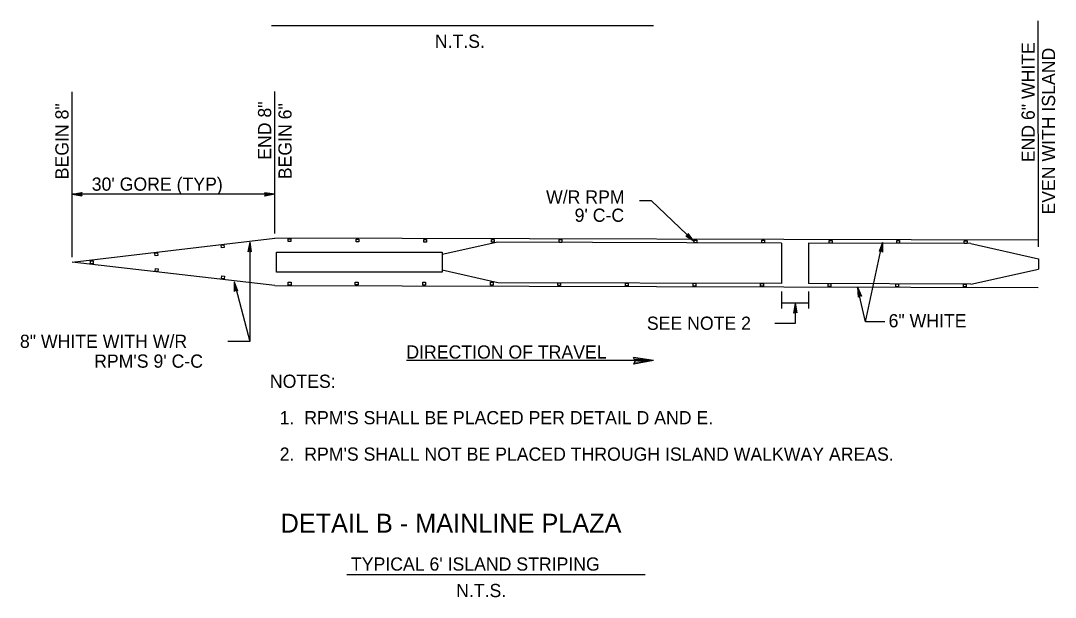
# Model space of a CAD drawing. Extents: x 583689 to 590775, y 1496016 to 1497365.
# Drawn here: x 587321 to 587869, y 1496480 to 1496786 of the extents above; entities that cross this region are included whole.
import ezdxf

# ---------------------------------------------------------------- set-up
doc = ezdxf.new("R2010")
doc.units = 0
for name, color, linetype in [('1', 7, 'Continuous'), ('10', 7, 'Continuous'), ('11', 7, 'Continuous'), ('21', 7, 'Continuous'), ('32', 7, 'Continuous'), ('50', 7, 'Continuous'), ('6', 7, 'Continuous'), ('TextNotes', 7, 'Continuous'), ('TextShtNo', 7, 'Continuous')]:
    doc.layers.add(name, color=color, linetype=linetype)

msp = doc.modelspace()

# ---------------------------------------------------------------- linework, layer by layer
at = {"layer": '10'}
for p, q in [((587573.89, 1496668.06), (587544.35, 1496661.49)), ((587724.16, 1496667.66), (587573.89, 1496668.06)), ((587724.16, 1496667.66), (587724.16, 1496646.19)), ((587824.44, 1496667.39), (587738.48, 1496667.62)), ((587738.48, 1496667.62), (587738.48, 1496646.15)), ((587824.44, 1496667.39), (587860.21, 1496659.24)), ((587544.35, 1496661.49), (587544.33, 1496653.31)), ((587860.21, 1496659.24), (587860.2, 1496653.87)), ((587824.38, 1496645.92), (587860.2, 1496653.87)), ((587573.84, 1496646.58), (587544.33, 1496653.31)), ((587724.16, 1496646.19), (587573.84, 1496646.58)), ((587824.38, 1496645.92), (587738.48, 1496646.15))]:
    msp.add_line(p, q, dxfattribs=at)
msp.add_lwpolyline([(587544.35, 1496662.8), (587544.35, 1496652.24), (587456.6, 1496652.24), (587456.6, 1496662.8)], close=True, dxfattribs=at)
at = {"layer": '11'}
for p, q in [((587348.36, 1496657.43), (587455.76, 1496670.16)), ((587860.24, 1496669.09), (587455.76, 1496670.16)), ((587455.72, 1496645.11), (587348.36, 1496657.43)), ((587455.72, 1496645.11), (587860.17, 1496644.04))]:
    msp.add_line(p, q, dxfattribs=at)
for points in [[(587428.87, 1496665.21), (587427.43, 1496665.06), (587427.28, 1496666.5), (587428.72, 1496666.65)], [(587464.16, 1496668.46), (587462.71, 1496668.46), (587462.71, 1496669.91), (587464.16, 1496669.91)], [(587500.27, 1496668.34), (587498.82, 1496668.34), (587498.82, 1496669.79), (587500.27, 1496669.79)], [(587536.14, 1496668.11), (587534.69, 1496668.11), (587534.69, 1496669.56), (587536.14, 1496669.56)], [(587571.93, 1496668.11), (587570.48, 1496668.11), (587570.48, 1496669.56), (587571.93, 1496669.56)], [(587607.72, 1496668.02), (587606.28, 1496668.02), (587606.28, 1496669.47), (587607.72, 1496669.47)], [(587679.27, 1496667.8), (587677.82, 1496667.8), (587677.82, 1496669.25), (587679.27, 1496669.25)], [(587715.15, 1496667.76), (587713.7, 1496667.76), (587713.7, 1496669.21), (587715.15, 1496669.21)], [(587750.9, 1496667.58), (587749.45, 1496667.58), (587749.45, 1496669.03), (587750.9, 1496669.03)], [(587786.6, 1496667.54), (587785.15, 1496667.54), (587785.15, 1496668.99), (587786.6, 1496668.99)], [(587822.44, 1496667.45), (587820.99, 1496667.45), (587820.99, 1496668.9), (587822.44, 1496668.9)], [(587393.7, 1496660.98), (587392.26, 1496660.82), (587392.11, 1496662.27), (587393.55, 1496662.42)], [(587359.47, 1496656.7), (587358.02, 1496656.7), (587358.02, 1496658.15), (587359.47, 1496658.15)], [(587393.76, 1496652.55), (587392.32, 1496652.71), (587392.49, 1496654.15), (587393.93, 1496653.99)], [(587428.93, 1496648.67), (587427.49, 1496648.83), (587427.66, 1496650.27), (587429.1, 1496650.1)], [(587464.27, 1496645.4), (587462.82, 1496645.4), (587462.82, 1496646.85), (587464.27, 1496646.85)], [(587499.79, 1496645.51), (587498.34, 1496645.51), (587498.34, 1496646.96), (587499.79, 1496646.96)], [(587535.55, 1496645.4), (587534.1, 1496645.4), (587534.1, 1496646.85), (587535.55, 1496646.85)], [(587571.35, 1496645.4), (587569.9, 1496645.4), (587569.9, 1496646.85), (587571.35, 1496646.85)], [(587607.09, 1496645.13), (587605.64, 1496645.13), (587605.64, 1496646.58), (587607.09, 1496646.58)], [(587642.97, 1496644.96), (587641.52, 1496644.96), (587641.52, 1496646.41), (587642.97, 1496646.41)], [(587678.77, 1496644.87), (587677.32, 1496644.87), (587677.32, 1496646.32), (587678.77, 1496646.32)], [(587714.52, 1496644.79), (587713.07, 1496644.79), (587713.07, 1496646.23), (587714.52, 1496646.23)], [(587750.31, 1496644.69), (587748.86, 1496644.69), (587748.86, 1496646.14), (587750.31, 1496646.14)], [(587786.19, 1496644.52), (587784.74, 1496644.52), (587784.74, 1496645.97), (587786.19, 1496645.97)], [(587821.98, 1496644.43), (587820.53, 1496644.43), (587820.53, 1496645.88), (587821.98, 1496645.88)]]:
    msp.add_lwpolyline(points, close=True, dxfattribs=at)
at = {"layer": '21'}
for p, q in [((587860.24, 1496665.69), (587860.19, 1496785.53)), ((587348.35, 1496660.2), (587348.31, 1496747.87)), ((587455.72, 1496672.63), (587455.69, 1496747.91)), ((587348.26, 1496693.49), (587353.46, 1496694.5)), ((587348.26, 1496693.49), (587353.26, 1496694.01)), ((587455.64, 1496693.49), (587348.26, 1496693.49)), ((587348.26, 1496693.49), (587353.5, 1496692.66)), ((587348.26, 1496693.49), (587353.27, 1496693.14)), ((587353.46, 1496694.5), (587353.08, 1496693.57)), ((587353.08, 1496693.57), (587353.5, 1496692.66)), ((587455.64, 1496693.49), (587450.41, 1496694.32)), ((587450.82, 1496693.41), (587450.41, 1496694.32)), ((587455.64, 1496693.49), (587450.44, 1496692.48)), ((587450.44, 1496692.48), (587450.82, 1496693.41)), ((587455.64, 1496693.49), (587450.63, 1496693.84)), ((587455.64, 1496693.49), (587450.64, 1496692.97)), ((587455.72, 1496673.08), (587455.71, 1496691.39)), ((587648.96, 1496690.18), (587655.16, 1496690.18)), ((587655.16, 1496690.18), (587677.7, 1496668.61)), ((587673.39, 1496671.38), (587674.28, 1496671.77)), ((587677.7, 1496668.61), (587673.39, 1496671.38)), ((587677.7, 1496668.61), (587673.86, 1496671.59)), ((587674.28, 1496671.77), (587674.6, 1496672.69)), ((587677.7, 1496668.61), (587674.44, 1496672.21)), ((587677.7, 1496668.61), (587674.6, 1496672.69)), ((587442.41, 1496668.03), (587441.42, 1496663.05)), ((587442.41, 1496668.03), (587441.89, 1496663.24)), ((587442.41, 1496668.03), (587442.39, 1496615.46)), ((587442.41, 1496668.03), (587443.18, 1496663.01)), ((587442.41, 1496668.03), (587442.72, 1496663.22)), ((587768.7, 1496625.82), (587777.65, 1496668.01)), ((587777.65, 1496668.01), (587775.82, 1496663.23)), ((587777.65, 1496668.01), (587776.31, 1496663.34)), ((587777.65, 1496668.01), (587777.14, 1496663.18)), ((587777.65, 1496668.01), (587777.56, 1496662.89)), ((587442.31, 1496663.41), (587441.42, 1496663.05)), ((587443.18, 1496663.01), (587442.31, 1496663.41)), ((587776.76, 1496663.44), (587775.82, 1496663.23)), ((587777.56, 1496662.89), (587776.76, 1496663.44)), ((587434.14, 1496647.06), (587442.39, 1496615.46)), ((587434.14, 1496647.06), (587434.14, 1496641.99)), ((587434.14, 1496647.06), (587435.88, 1496642.29)), ((587434.14, 1496647.06), (587435.38, 1496642.41)), ((587434.14, 1496647.06), (587434.56, 1496642.27)), ((587764.37, 1496644.29), (587764.76, 1496639.01)), ((587764.37, 1496644.29), (587766.54, 1496639.46)), ((587764.37, 1496644.29), (587766.02, 1496639.54)), ((587764.37, 1496644.29), (587765.17, 1496639.33)), ((587768.7, 1496625.82), (587764.37, 1496644.29)), ((587434.94, 1496642.52), (587434.14, 1496641.99)), ((587435.88, 1496642.29), (587434.94, 1496642.52)), ((587724.16, 1496641.95), (587724.16, 1496632.95)), ((587738.47, 1496641.94), (587738.47, 1496632.94)), ((587765.55, 1496639.62), (587764.76, 1496639.01)), ((587766.54, 1496639.46), (587765.55, 1496639.62)), ((587738.47, 1496635.78), (587724.16, 1496635.79)), ((587731.31, 1496635.78), (587730.48, 1496630.55)), ((587731.31, 1496635.78), (587730.96, 1496630.77)), ((587731.31, 1496635.78), (587731.31, 1496624.93)), ((587731.31, 1496635.78), (587732.32, 1496630.58)), ((587731.31, 1496635.78), (587731.84, 1496630.78)), ((587731.4, 1496630.96), (587730.48, 1496630.55)), ((587732.32, 1496630.58), (587731.4, 1496630.96)), ((587731.31, 1496624.93), (587720.66, 1496624.93)), ((587778.9, 1496625.82), (587768.7, 1496625.82)), ((587442.39, 1496615.46), (587430.88, 1496615.46)), ((587656.25, 1496605.39), (587552.51, 1496605.39)), ((587656.25, 1496605.39), (587645.79, 1496607.05)), ((587646.62, 1496605.22), (587645.79, 1496607.05)), ((587656.25, 1496605.39), (587645.85, 1496603.37)), ((587645.85, 1496603.37), (587646.62, 1496605.22)), ((587656.25, 1496605.39), (587646.23, 1496606.09)), ((587656.25, 1496605.39), (587646.25, 1496604.34)), ((587493.82, 1496491.87), (587651.82, 1496491.87))]:
    msp.add_line(p, q, dxfattribs=at)
at = {"layer": '32'}
msp.add_line((587454.02, 1496783.02), (587656.27, 1496783.04), dxfattribs=at)
at = {"layer": 'TextShtNo'}
msp.add_line((587552.51, 1496605.39), (587525.38, 1496605.39), dxfattribs=at)

# ---------------------------------------------------------------- texts
at = {"layer": '1'}
msp.add_text('N.T.S.', height=7, rotation=0.0047, dxfattribs=at).set_placement((587540.47, 1496771.13))
at = {"layer": '21'}
for s, p in [("30' GORE (TYP)", (587358.7, 1496695.39)), ('W/R RPM', (587599.41, 1496688.56)), ("9' C-C", (587614.53, 1496678.91)), ('SEE NOTE 2', (587652.81, 1496621.65)), ('6" WHITE', (587780.86, 1496622.97)), ('DIRECTION OF TRAVEL', (587525.38, 1496606.4))]:
    msp.add_text(s, height=7, dxfattribs=at).set_placement(p)
at = {"layer": '50'}
for s, p in [('END 6" WHITE', (587858.29, 1496710.48)), ('EVEN WITH ISLAND', (587869.09, 1496682.75)), ('BEGIN 8"', (587346.41, 1496701.45)), ('END 8"', (587453.79, 1496711.79)), ('BEGIN 6"', (587464.59, 1496701.5))]:
    msp.add_text(s, height=7, rotation=90, dxfattribs=at).set_placement(p)
for s, p in [('8" WHITE WITH W/R', (587320.65, 1496612.06)), ("RPM'S 9' C-C", (587359.97, 1496601.56))]:
    msp.add_text(s, height=7, dxfattribs=at).set_placement(p)
at = {"layer": '6'}
for s, height, p in [('DETAIL B - MAINLINE PLAZA', 10, (587458.75, 1496514.16)), ("TYPICAL 6' ISLAND STRIPING", 7, (587496.02, 1496493.99)), ('N.T.S.', 7, (587551.75, 1496479.95))]:
    msp.add_text(s, height=height, rotation=359.9987, dxfattribs=at).set_placement(p)
at = {"layer": 'TextNotes'}
for s, p in [('NOTES:', (587453.08, 1496590.89)), ("  1.  RPM'S SHALL BE PLACED PER DETAIL D AND E.", (587453.08, 1496571.58)), ("  2.  RPM'S SHALL NOT BE PLACED THROUGH ISLAND WALKWAY AREAS.", (587453.08, 1496552.26))]:
    msp.add_text(s, height=7, dxfattribs=at).set_placement(p)

doc.saveas('drawing.dxf')
